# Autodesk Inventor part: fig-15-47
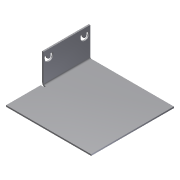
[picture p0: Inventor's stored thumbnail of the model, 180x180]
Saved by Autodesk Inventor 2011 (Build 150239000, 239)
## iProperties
Created: 2005-03
Part Number: fig-15-47
Document SubType Name: Sheet Metal
Designer: CADCIM
Manufacturer: Standard
Standards Organization: Custom
Density: 1 g/cm^3
Sheet Metal Rule: Default
Author: CADCIM
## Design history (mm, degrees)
node "Face1"
  sketch "Sketch1"
    geometry: L1 (-29, -26)-(30, -26); L2 (30, -26)-(30, 31.375); L3 (30, 31.375)-(-29, 31.375); L4 (-29, 31.375)-(-29, -26)
    constraints: 8 end point, 2 parallel, 1 horizontal, 1 perpendicular
node "Flange1"
sketch "Sketch4"
  geometry: L1 (3.278, 0.812)-(4.721, 0.812); L2 (4.721, 6.681)-(3.278, 6.681); L3 (3.278, 4.946)-(4.721, 4.946); L4 (4.721, 2.546)-(3.278, 2.546); L5 (3.278, 0.812)-(3.278, 2.546); L6 (3.278, 4.946)-(3.278, 6.681); L7 (3.278, 31.563)-(4.721, 31.563); L8 (4.721, 25.694)-(3.278, 25.694); L9 (3.278, 27.429)-(4.721, 27.429); L10 (4.721, 29.829)-(3.278, 29.829); L11 (3.278, 31.563)-(3.278, 29.829); L12 (3.278, 27.429)-(3.278, 25.694); A1 r 2.935 centre (4.721, 3.746) between (4.721, 0.812) and (4.721, 6.681); A2 r 1.2 centre (4.721, 3.746) between (4.721, 2.546) and (4.721, 4.946); A3 r 2.935 centre (4.721, 28.629) between (4.721, 25.694) and (4.721, 31.563); A4 r 1.2 centre (4.721, 28.629) between (4.721, 27.429) and (4.721, 29.829)
  constraints: 24 end point, 8 point on circle, 4 centre point, 3 equal length, 2 tangent, 1 horizontal, 1 perpendicular, 1 vertical alignment, 2 other
cut "Cut1" sketch "Sketch4" dims "d20" = 1 (= Thickness), "d21" = 0
body "Solid1"
face "Plate1" dims "Thickness" = 1
sketch "Sketch2"
  geometry: L1 (25, 0)-(57.375, 0); L2 (57.375, 0)-(57.375, 20); L3 (57.375, 20)-(25, 20); L4 (25, 20)-(25, 0)
  constraints: 8 end point
face "Plate2" dims "d1" = 0, "d2" = 25, "d3" = 1 (= BendReliefWidth), "d5" = 2 (= MinimumRemnant), "d7" = 20, "d8" = 90 deg, "d9" = 1 (= BendRadius), "Thickness" = 1
bend "Bend1" dims "d3" = 1 (= BendReliefWidth), "d4" = 0.5 (= BendReliefDepth), "d5" = 2 (= MinimumRemnant), "d6" = 1 (= BendRadius), "d7" = 20, "d8" = 90 deg, "d9" = 1 (= BendRadius), "SeamGap" = 0.01, "Thickness" = 1
other parameters: "BendRadius" = 1 (= Thickness), "BendReliefWidth" = 1 (= Thickness), "BendReliefDepth" = 0.5 (= 0.5 x Thickness), "CornerReliefSize" = 4 (= 4 x Thickness), "MinimumRemnant" = 2 (= 2 x Thickness), "TransitionRadius" = 1 (= BendRadius), "d0" = 1 (= BendRadius), "JacobiRadiusSize" = 1 (= Thickness), "GapSize" = 1 (= Thickness)
